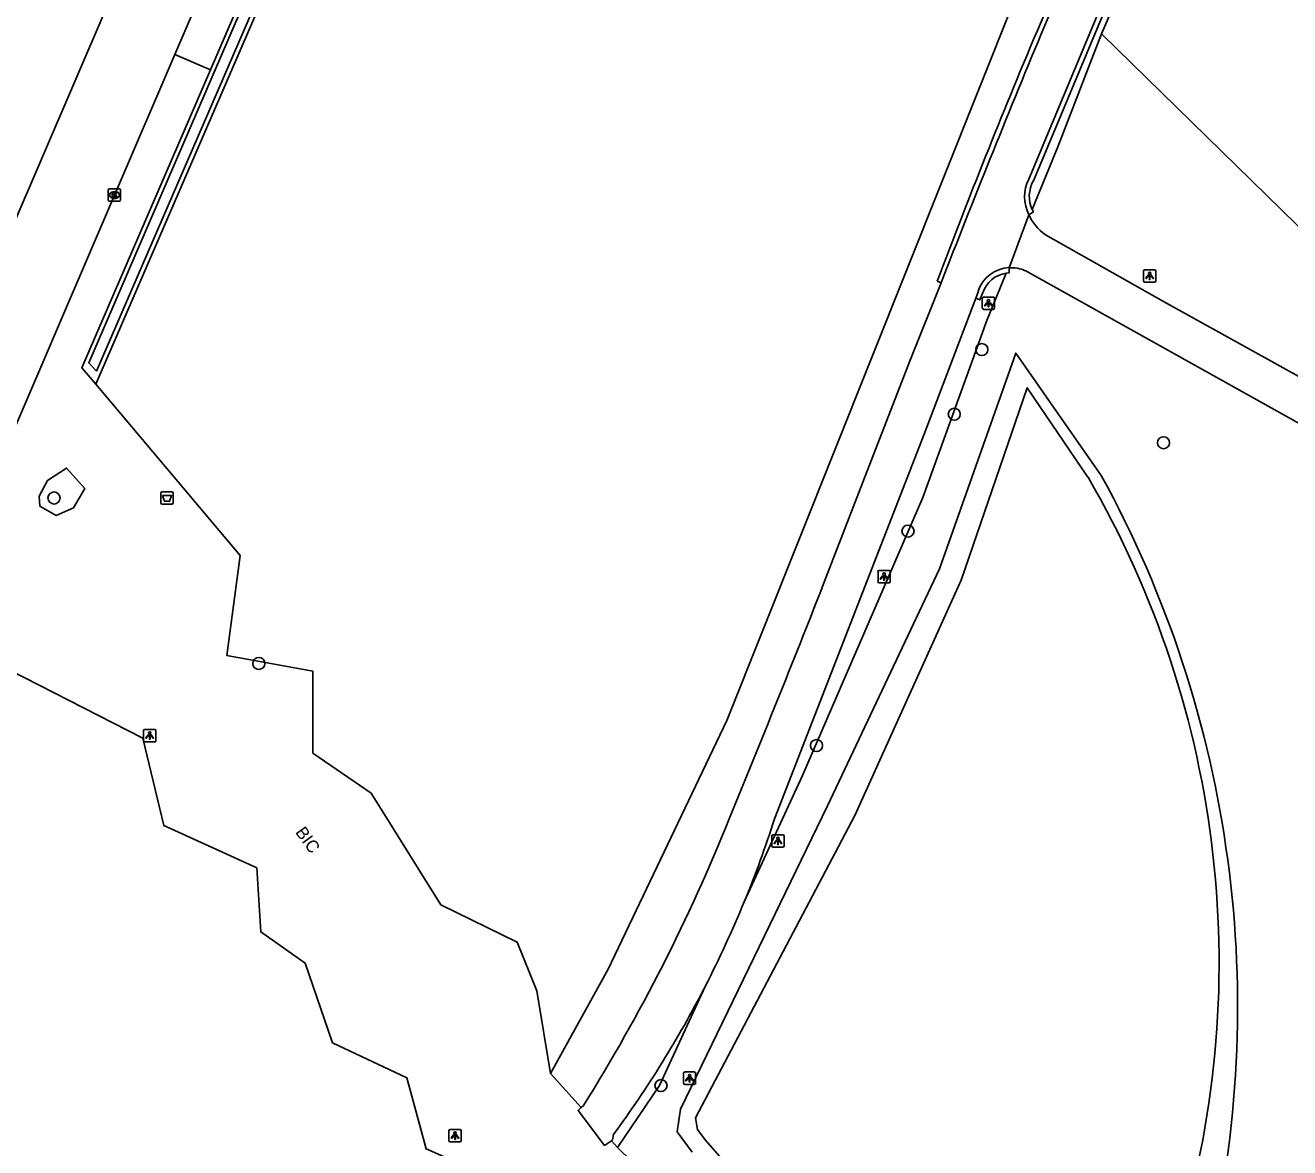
# Model space of a CAD drawing. Extents: x 155209 to 156823, y 385356 to 388482.
# Drawn here: x 155937 to 156039.5, y 385947.3 to 386038.3 of the extents above; entities that cross this region are included whole.
import ezdxf

# ---------------------------------------------------------------- set-up
doc = ezdxf.new("R2010")
doc.units = 0
for name, color, linetype in [('IMGEO_Afvalbak', 7, 'Continuous'), ('IMGEO_Berm_groen', 7, 'Continuous'), ('IMGEO_Berm_open', 7, 'Continuous'), ('IMGEO_Boom', 7, 'Continuous'), ('IMGEO_Groenvoorziening', 7, 'Continuous'), ('IMGEO_Kolk', 7, 'Continuous'), ('IMGEO_Lichtpunt', 7, 'Continuous'), ('IMGEO_Loofbos', 7, 'Continuous'), ('IMGEO_Meer_plas_ven_vijver', 7, 'Continuous'), ('IMGEO_Naaldbos', 7, 'Continuous'), ('IMGEO_Openbare_ruimte_label', 7, 'Continuous'), ('IMGEO_Rijbaan_lokaal_gesloten', 7, 'Continuous'), ('IMGEO_Voetpad_gesloten', 7, 'Continuous'), ('IMGEO_Voetpad_open', 7, 'Continuous'), ('IMGEO_Waterloop', 7, 'Continuous')]:
    doc.layers.add(name, color=color, linetype=linetype)

msp = doc.modelspace()

# ---------------------------------------------------------------- linework, layer by layer
at = {"layer": 'IMGEO_Afvalbak'}
for p, q in [((155948.1, 386000.47), (155948.89, 386000.47)), ((155948.89, 386000.47), (155948.1, 386000.47)), ((155948, 385999.57), (155948, 386000.37)), ((155948, 386000.37), (155948, 385999.57)), ((155948.89, 385999.47), (155948.1, 385999.47)), ((155948.1, 385999.47), (155948.89, 385999.47)), ((155948.99, 386000.37), (155948.99, 385999.57)), ((155948.99, 385999.57), (155948.99, 386000.37))]:
    msp.add_line(p, q, dxfattribs=at)
msp.add_lwpolyline([(155948.14, 386000.18), (155948.85, 386000.18), (155948.7, 385999.71), (155948.29, 385999.71), (155948.14, 386000.18)], dxfattribs=at)
for centre, start, end in [((155948.1, 386000.37), 90, 180), ((155948.1, 386000.37), 90, 180), ((155948.89, 386000.37), 0, 90), ((155948.89, 386000.37), 360, 90), ((155948.1, 385999.57), 180, 270), ((155948.1, 385999.57), 180, 270), ((155948.89, 385999.57), 270, 0), ((155948.89, 385999.57), 270, 0)]:
    msp.add_arc(centre, 0.1, start, end, dxfattribs=at)
at = {"layer": 'IMGEO_Berm_groen'}
for points in [[(156013.5, 386177.7), (156000, 386146), (155952.02, 386034.68)], [(156024.22, 386037.59), (156045.81, 386087.34), (156049.5, 386095.21), (156057.59, 386112.46), (156071.11, 386138.48), (156074.02, 386139.6), (156094.02, 386125.25)], [(156017.22, 386040.43), (155993.88, 385981.94), (155984.26, 385961.78), (155979.58, 385953.33)], [(156018.62, 386023.35), (156020.7, 386028.43), (156024.22, 386037.59)]]:
    msp.add_lwpolyline(points, dxfattribs=at)
at = {"layer": 'IMGEO_Berm_open'}
for points in [[(156042.89, 386082.44), (156038.86, 386073.22), (156030.85, 386054.72), (156018.71, 386025.67)], [(156018.96, 386037.69), (156023.47, 386048.35), (156027.93, 386058.88), (156029.15, 386061.75), (156028.19, 386062.62), (156028.36, 386063)], [(156018.34, 386022.93), (156018.71, 386023.16), (156018.62, 386023.35)], [(156016.74, 386018.64), (156016.74, 386018.21), (156016.51, 386018.2)], [(156011.24, 386017.42), (156010.92, 386017.54)], [(156014.61, 386016.62), (156014.36, 386016.03), (156014.04, 386016.16)]]:
    msp.add_lwpolyline(points, dxfattribs=at)
for centre, radius, start, end in [((156557.9, 385810.82), 584.75, 157.17081, 159.29698), ((156020.96, 386024.42), 2.58, 151.0324, 204.678), ((156016.82, 386015.89), 2.32, 97.6097, 161.8767)]:
    msp.add_arc(centre, radius, start, end, dxfattribs=at)
at = {"layer": 'IMGEO_Boom'}
for centre in [(156014.53, 386012), (156012.3, 386006.76), (156029.26, 386004.45), (155939.34, 385999.97), (156008.55, 385997.29), (155955.94, 385986.56), (156001.13, 385979.9), (155988.53, 385952.34)]:
    msp.add_circle(centre, 0.489, dxfattribs=at)
at = {"layer": 'IMGEO_Groenvoorziening'}
for points in [[(155995.28, 385967.24), (156000, 385977.48), (156009.75, 386000), (156014.95, 386014.37), (156016.51, 386018.2)], [(155991.07, 385946.93), (155989.85, 385948.58), (155990.11, 385950.43), (156002.03, 385975.02), (156011.1, 385994.24), (156017.28, 386011.72), (156024.21, 386001.79)], [(155992.11, 385960.36), (155988.41, 385952.34), (155985, 385947.32)]]:
    msp.add_lwpolyline(points, dxfattribs=at)
msp.add_arc((155945.74, 385958.71), 89.52, 346.5304, 28.7684, dxfattribs=at)
at = {"layer": 'IMGEO_Kolk'}
for p, q in [((155943.81, 386025.03), (155944.67, 386025.03)), ((155943.74, 386024.1), (155943.74, 386024.95)), ((155944.67, 386024.03), (155943.81, 386024.03)), ((155944.23, 386024.81), (155944.25, 386024.81)), ((155944.25, 386024.25), (155944.23, 386024.25)), ((155944.74, 386024.95), (155944.74, 386024.1))]:
    msp.add_line(p, q, dxfattribs=at)
for points in [[(155943.81, 386025.03), (155944.67, 386025.03)], [(155943.74, 386024.1), (155943.74, 386024.95)], [(155944.67, 386024.03), (155943.81, 386024.03)], [(155944.06, 386024.73), (155944.18, 386024.73), (155944.18, 386024.57), (155944.31, 386024.73), (155944.48, 386024.73), (155944.33, 386024.58), (155944.48, 386024.33), (155944.33, 386024.33), (155944.25, 386024.49), (155944.18, 386024.42), (155944.18, 386024.33), (155944.06, 386024.33), (155944.06, 386024.73)], [(155944.74, 386024.95), (155944.74, 386024.1)]]:
    msp.add_lwpolyline(points, dxfattribs=at)
for centre, start, end in [((155943.82, 386024.95), 91.552, 178.448), ((155943.82, 386024.95), 91.552, 178.448), ((155944.66, 386024.95), 1.552, 88.448), ((155944.66, 386024.95), 1.552, 88.448), ((155943.82, 386024.1), 181.552, 268.448), ((155943.82, 386024.1), 181.552, 268.448), ((155944.66, 386024.1), 271.552, 358.448), ((155944.66, 386024.1), 271.552, 358.448)]:
    msp.add_arc(centre, 0.0765, start, end, dxfattribs=at)
for centre, major_axis, ratio, start_param, end_param in [((155944.23, 386024.53), (-0.387, 0.002), 0.722429, 4.712389, 7.853982), ((155944.25, 386024.53), (-0.39, 0.002), 0.717154, 1.570796, 4.712389)]:
    msp.add_ellipse(centre, major_axis=major_axis, ratio=ratio, start_param=start_param, end_param=end_param, dxfattribs=at)
at = {"layer": 'IMGEO_Lichtpunt'}
for p, q in [((156027.64, 386018.37), (156027.64, 386017.57)), ((156027.64, 386018.37), (156027.64, 386017.57)), ((156028.54, 386018.47), (156027.73, 386018.47)), ((156028.54, 386018.47), (156027.73, 386018.47)), ((156028.64, 386017.57), (156028.64, 386018.37)), ((156028.64, 386017.57), (156028.64, 386018.37)), ((156027.73, 386017.47), (156028.54, 386017.47)), ((156027.73, 386017.47), (156028.54, 386017.47)), ((156014.57, 386016.16), (156014.57, 386015.36)), ((156014.57, 386016.16), (156014.57, 386015.36)), ((156015.47, 386016.26), (156014.67, 386016.26)), ((156015.47, 386016.26), (156014.67, 386016.26)), ((156015.57, 386015.36), (156015.57, 386016.16)), ((156015.57, 386015.36), (156015.57, 386016.16)), ((156014.67, 386015.26), (156015.47, 386015.26)), ((156014.67, 386015.26), (156015.47, 386015.26)), ((156006.12, 385994.01), (156006.12, 385993.2)), ((156006.12, 385994.01), (156006.12, 385993.2)), ((156007.02, 385994.1), (156006.21, 385994.1)), ((156007.02, 385994.1), (156006.21, 385994.1)), ((156007.11, 385993.2), (156007.11, 385994.01)), ((156007.11, 385993.2), (156007.11, 385994.01)), ((156006.21, 385993.1), (156007.02, 385993.1)), ((156006.21, 385993.1), (156007.02, 385993.1)), ((155946.6, 385981.11), (155946.6, 385980.31)), ((155946.6, 385981.11), (155946.6, 385980.31)), ((155947.5, 385981.21), (155946.69, 385981.21)), ((155947.5, 385981.21), (155946.69, 385981.21)), ((155947.59, 385980.31), (155947.59, 385981.11)), ((155947.59, 385980.31), (155947.59, 385981.11)), ((155946.69, 385980.21), (155947.5, 385980.21)), ((155946.69, 385980.21), (155947.5, 385980.21)), ((155997.51, 385972.57), (155997.51, 385971.77)), ((155997.51, 385972.57), (155997.51, 385971.77)), ((155998.41, 385972.67), (155997.61, 385972.67)), ((155998.41, 385972.67), (155997.61, 385972.67)), ((155998.51, 385971.77), (155998.51, 385972.57)), ((155998.51, 385971.77), (155998.51, 385972.57)), ((155997.61, 385971.67), (155998.41, 385971.67)), ((155997.61, 385971.67), (155998.41, 385971.67)), ((155990.35, 385953.34), (155990.35, 385952.54)), ((155990.35, 385953.34), (155990.35, 385952.54)), ((155991.25, 385953.44), (155990.44, 385953.44)), ((155991.25, 385953.44), (155990.44, 385953.44)), ((155991.34, 385952.54), (155991.34, 385953.34)), ((155991.34, 385952.54), (155991.34, 385953.34)), ((155990.44, 385952.44), (155991.25, 385952.44)), ((155990.44, 385952.44), (155991.25, 385952.44)), ((155971.34, 385948.68), (155971.34, 385947.88)), ((155971.34, 385948.68), (155971.34, 385947.88)), ((155972.24, 385948.78), (155971.44, 385948.78)), ((155972.24, 385948.78), (155971.44, 385948.78)), ((155972.34, 385947.88), (155972.34, 385948.68)), ((155972.34, 385947.88), (155972.34, 385948.68)), ((155971.44, 385947.78), (155972.24, 385947.78)), ((155971.44, 385947.78), (155972.24, 385947.78))]:
    msp.add_line(p, q, dxfattribs=at)
for points in [[(156028.01, 386018.04), (156028.05, 386018.01), (156027.86, 386017.75), (156027.83, 386017.78), (156028.01, 386018.04)], [(156028.11, 386017.99), (156028.16, 386017.99), (156028.16, 386017.67), (156028.11, 386017.67), (156028.11, 386017.99)], [(156028.22, 386018.01), (156028.26, 386018.04), (156028.45, 386017.77), (156028.41, 386017.75), (156028.22, 386018.01)], [(156014.95, 386015.83), (156014.99, 386015.8), (156014.8, 386015.54), (156014.76, 386015.56), (156014.95, 386015.83)], [(156015.16, 386015.8), (156015.2, 386015.83), (156015.38, 386015.56), (156015.35, 386015.54), (156015.16, 386015.8)], [(156015.05, 386015.78), (156015.1, 386015.78), (156015.1, 386015.46), (156015.05, 386015.46), (156015.05, 386015.78)], [(156006.49, 385993.67), (156006.53, 385993.64), (156006.34, 385993.38), (156006.3, 385993.41), (156006.49, 385993.67)], [(156006.59, 385993.62), (156006.64, 385993.62), (156006.64, 385993.3), (156006.59, 385993.3), (156006.59, 385993.62)], [(156006.7, 385993.64), (156006.74, 385993.67), (156006.93, 385993.41), (156006.89, 385993.38), (156006.7, 385993.64)], [(155946.97, 385980.78), (155947.01, 385980.75), (155946.82, 385980.49), (155946.78, 385980.52), (155946.97, 385980.78)], [(155947.07, 385980.73), (155947.12, 385980.73), (155947.12, 385980.41), (155947.07, 385980.41), (155947.07, 385980.73)], [(155947.18, 385980.75), (155947.22, 385980.78), (155947.41, 385980.51), (155947.37, 385980.49), (155947.18, 385980.75)], [(155997.89, 385972.24), (155997.92, 385972.21), (155997.74, 385971.95), (155997.7, 385971.97), (155997.89, 385972.24)], [(155997.99, 385972.19), (155998.03, 385972.19), (155998.03, 385971.87), (155997.99, 385971.87), (155997.99, 385972.19)], [(155998.1, 385972.21), (155998.14, 385972.24), (155998.32, 385971.97), (155998.28, 385971.95), (155998.1, 385972.21)], [(155990.72, 385953.01), (155990.76, 385952.98), (155990.57, 385952.72), (155990.53, 385952.74), (155990.72, 385953.01)], [(155990.82, 385952.96), (155990.87, 385952.96), (155990.87, 385952.64), (155990.82, 385952.64), (155990.82, 385952.96)], [(155990.93, 385952.98), (155990.97, 385953.01), (155991.16, 385952.74), (155991.12, 385952.72), (155990.93, 385952.98)], [(155971.72, 385948.35), (155971.76, 385948.32), (155971.57, 385948.06), (155971.53, 385948.09), (155971.72, 385948.35)], [(155971.82, 385948.3), (155971.87, 385948.3), (155971.87, 385947.98), (155971.82, 385947.98), (155971.82, 385948.3)], [(155971.93, 385948.32), (155971.97, 385948.35), (155972.15, 385948.08), (155972.12, 385948.06), (155971.93, 385948.32)]]:
    msp.add_lwpolyline(points, dxfattribs=at)
for centre in [(156028.14, 386018.17), (156015.07, 386015.96), (156006.62, 385993.8), (155947.1, 385980.91), (155998.01, 385972.37), (155990.85, 385953.14), (155971.84, 385948.48)]:
    msp.add_circle(centre, 0.0994, dxfattribs=at)
for centre, start, end in [((156027.73, 386018.37), 90, 180), ((156027.73, 386018.37), 90, 180), ((156028.54, 386018.37), 0, 90), ((156028.54, 386018.37), 0, 90), ((156027.73, 386017.57), 180, 270), ((156027.73, 386017.57), 180, 270), ((156028.54, 386017.57), 270, 0), ((156028.54, 386017.57), 270, 360), ((156014.67, 386016.16), 90, 180), ((156014.67, 386016.16), 90, 180), ((156015.47, 386016.16), 0, 90), ((156015.47, 386016.16), 0, 90), ((156014.67, 386015.36), 180, 270), ((156014.67, 386015.36), 180, 270), ((156015.47, 386015.36), 270, 0), ((156015.47, 386015.36), 270, 360), ((156006.21, 385994.01), 90, 180), ((156006.21, 385994.01), 90, 180), ((156007.02, 385994.01), 0, 90), ((156007.02, 385994.01), 0, 90), ((156006.21, 385993.2), 180, 270), ((156006.21, 385993.2), 180, 270), ((156007.02, 385993.2), 270, 0), ((156007.02, 385993.2), 270, 360), ((155946.69, 385981.11), 90, 180), ((155946.69, 385981.11), 90, 180), ((155947.5, 385981.11), 0, 90), ((155947.5, 385981.11), 0, 90), ((155946.69, 385980.31), 180, 270), ((155946.69, 385980.31), 180, 270), ((155947.5, 385980.31), 270, 0), ((155947.5, 385980.31), 270, 360), ((155997.61, 385972.57), 90, 180), ((155997.61, 385972.57), 90, 180), ((155997.61, 385971.77), 180, 270), ((155997.61, 385971.77), 180, 270), ((155998.41, 385972.57), 0, 90), ((155998.41, 385972.57), 0, 90), ((155998.41, 385971.77), 270, 0), ((155998.41, 385971.77), 270, 360), ((155990.44, 385953.34), 90, 180), ((155990.44, 385953.34), 90, 180), ((155991.25, 385953.34), 0, 90), ((155991.25, 385953.34), 0, 90), ((155990.44, 385952.54), 180, 270), ((155990.44, 385952.54), 180, 270), ((155991.25, 385952.54), 270, 0), ((155991.25, 385952.54), 270, 360), ((155971.44, 385948.68), 90, 180), ((155971.44, 385948.68), 90, 180), ((155972.24, 385948.68), 0, 90), ((155972.24, 385948.68), 0, 90), ((155971.44, 385947.88), 180, 270), ((155971.44, 385947.88), 180, 270), ((155972.24, 385947.88), 270, 0), ((155972.24, 385947.88), 270, 360)]:
    msp.add_arc(centre, 0.0946, start, end, dxfattribs=at)
at = {"layer": 'IMGEO_Loofbos'}
msp.add_lwpolyline([(156024.22, 386037.59), (156068.01, 385994.76)], dxfattribs=at)
at = {"layer": 'IMGEO_Meer_plas_ven_vijver'}
for points in [[(156023.13, 386001.65), (156018.22, 386008.91), (156012.86, 385993.3), (156004.23, 385974.24), (155991.34, 385949.73), (155991.49, 385948.79), (155992.11, 385947.95)], [(155992.11, 385947.95), (156018.56, 385917.78), (156025.62, 385928.76), (156030.21, 385938.97)]]:
    msp.add_lwpolyline(points, dxfattribs=at)
msp.add_arc((155955.43, 385962.27), 78.33, 342.6984, 30.1872, dxfattribs=at)
at = {"layer": 'IMGEO_Naaldbos'}
msp.add_lwpolyline([(155942.72, 386009.19), (155975.71, 386085.5)], dxfattribs=at)
at = {"layer": 'IMGEO_Rijbaan_lokaal_gesloten'}
for points in [[(156003.54, 386179.53), (155989.7, 386147.22), (155959.53, 386076.88), (155927.74, 386002.82)], [(155949.14, 386035.92), (155965.64, 386074.34), (155984.91, 386119.23), (156009.58, 386176.82)], [(156018.34, 386025.82), (156030.47, 386054.89), (156038.47, 386073.36), (156042.51, 386082.62)], [(156038.74, 386082.69), (156029.56, 386061.6), (156023.82, 386048.16), (156019.32, 386037.52)], [(155929.14, 385989.38), (155934.02, 386000.73), (155944.24, 386024.53), (155949.14, 386035.92)], [(156016.74, 386018.64), (156018.34, 386022.93)], [(156011.24, 386017.42), (156008.73, 386011.15), (156004.89, 386001.24), (156001.71, 385993.01)], [(155997.73, 385973.97), (156009.86, 386005.14), (156014.04, 386016.16)], [(156014.04, 386016.16), (156014.25, 386016.74)], [(155982.07, 385950.57), (155981.81, 385950.33), (155983.96, 385947.49), (155984.51, 385947.86)], [(155982.25, 385950.72), (155982.07, 385950.57)], [(155984.51, 385947.86), (155984.61, 385947.94), (155984.67, 385948.36)]]:
    msp.add_lwpolyline(points, dxfattribs=at)
for centre, radius, start, end in [((156846.13, 385693.33), 895.59, 157.39848, 158.78459), ((156021.18, 386024.38), 3.18, 153.107, 207.1309), ((156016.88, 386015.88), 2.77, 92.869, 161.8512), ((154574.46, 386555.24), 1534, 337.73306, 338.49917), ((155857.09, 386028.96), 147.6, 327.9903, 338.127), ((155913.88, 386000.64), 87.99, 337.6916, 342.3572), ((155913.43, 386000.81), 88.46, 332.7924, 337.6986), ((155913.4, 386000.83), 88.5, 323.6332, 332.7845)]:
    msp.add_arc(centre, radius, start, end, dxfattribs=at)
at = {"layer": 'IMGEO_Voetpad_gesloten'}
for points in [[(156019.69, 386021.3), (156029.26, 386015.9), (156063.85, 385996.7), (156068.01, 385994.76)], [(156041.46, 386005.34), (156018.05, 386018.4)]]:
    msp.add_lwpolyline(points, dxfattribs=at)
for centre, radius, start, end in [((156021.87, 386024.48), 3.85, 203.6198, 235.4213), ((156016.88, 386015.69), 2.95, 66.5786, 92.6733)]:
    msp.add_arc(centre, radius, start, end, dxfattribs=at)
at = {"layer": 'IMGEO_Voetpad_open'}
for points in [[(155952.02, 386034.68), (155949.14, 386035.92)], [(155942.72, 386009.19), (155941.6, 386010.52), (155952.02, 386034.68)], [(155979.58, 385953.33), (155978.47, 385960.03), (155976.88, 385963.96), (155970.69, 385967), (155965.05, 385976.04), (155960.31, 385979.29), (155960.31, 385985.94), (155953.35, 385987.2), (155954.43, 385995.3), (155942.72, 386009.19)], [(155938.18, 385999.31), (155938.14, 386000.11), (155938.8, 386001.39), (155940.36, 386002.4), (155941.83, 386000.74), (155940.93, 385999.18), (155939.52, 385998.54), (155938.18, 385999.31)], [(155933.29, 385987.26), (155946.55, 385980.5), (155948.24, 385973.41), (155955.77, 385969.98), (155956.09, 385964.8), (155959.69, 385962.26), (155961.9, 385955.8), (155967.94, 385952.96), (155969.49, 385947.2), (155974.75, 385944.88)], [(155982.07, 385950.57), (155979.58, 385953.33)], [(155985, 385947.32), (155984.51, 385947.86)], [(156019.47, 385903.8), (156017.52, 385906.07), (156018.53, 385908.45), (156008.31, 385921.43), (156005.3, 385921.16), (156005.3, 385926.18), (156002.75, 385928.69), (156002.22, 385930.59), (155997.57, 385935.14), (155994.61, 385935.3), (155993.71, 385936.3), (155994.5, 385938.05), (155985, 385947.32)]]:
    msp.add_lwpolyline(points, dxfattribs=at)
at = {"layer": 'IMGEO_Waterloop'}
for points in [[(156015.54, 386179.18), (156015.76, 386179.19), (156015.84, 386179.15), (156015.91, 386178.56), (156028.73, 386169.96), (156048.81, 386156.86), (156048.58, 386156.51), (156048.41, 386156.24), (156033.05, 386166.23), (156015.52, 386177.85), (156015.03, 386177.92), (156014.67, 386177.6), (156000.35, 386144.53), (155999.67, 386142.97), (155975.09, 386085.85), (155975.31, 386085.48), (155942.79, 386010.26)], [(155942.79, 386010.26), (155942.16, 386010.92), (156000.33, 386145.86), (156013.83, 386177.55)]]:
    msp.add_lwpolyline(points, dxfattribs=at)

# ---------------------------------------------------------------- texts
at = {"layer": 'IMGEO_Openbare_ruimte_label'}
msp.add_text('BIC', height=1, rotation=306.0105, dxfattribs=at).set_placement((155958.85, 385972.87))

doc.saveas('drawing.dxf')
